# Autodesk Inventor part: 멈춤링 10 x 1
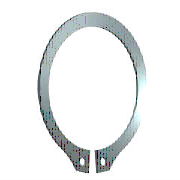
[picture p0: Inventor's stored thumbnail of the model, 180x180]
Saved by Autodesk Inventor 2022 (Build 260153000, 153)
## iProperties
Created: 2021-07
Part Number: 멈춤링 10 x 1
Material: 강철, 연강
Description: 리테이닝 링(C형)
Document SubType Name: Modeling
Standard: KS B 1336
Designer: mdu
Standards Organization: KS
Language: ko-KR
Size Designation: 10 x 1
Categories: <MemberInstance><Categories><Category DisplayName="샤프트 부품" InternalName="7f7aeb1f-a693-4053-b835-cee3144e0d98" Mnemonic="SHFT"><Category DisplayName="써클립" Inter
Density: 7.86 g/cm^3
Mass: 0.423084 g
Surface Area: 1.9243 cm^2
Volume: 0.0538275 cm^3
Appearance: 파란색 - 벽 페인트 - 광택
IsCustomPart: 0
Author: mdu
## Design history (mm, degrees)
sketch "스케치1"
  geometry: L1 (-6, 0)-(6, 0) reference; L2 (0, 20.189)-(0, -80.536) reference; L3 (-48.09, 0)-(48.09, 0) reference; L4 (-0.3, -9.791)-(-0.3, -12.791); L5 (-0.3, -6.54)-(-0.3, -13.29); L6 (-2.795, 1.6)-(3.672, 1.6); L7 (0.3, -6.54)-(0.3, -13.29); L8 (0.3, -9.791)-(0.3, -12.791); C1 r 0.6 at (-1.2, -11.486); C2 r 0.6 at (1.2, -11.486); A1 r 4.8 centre (0, -5) between (0.3, -9.791) and (-0.3, -9.791); A2 r 6.2 centre (0, -4.6) between (2.988, -10.033) and (-2.988, -10.033); A3 r 7.796 centre (0, -5) between (-1.418, -12.666) and (-0.3, -12.791); A4 r 1.2 centre (-1.2, -11.486) between (-2.383, -11.285) and (-1.418, -12.666); A5 r 1.2 centre (-3.566, -11.084) between (-2.383, -11.285) and (-2.988, -10.033); A6 r 1.2 centre (3.566, -11.084) between (2.988, -10.033) and (2.383, -11.285); A7 r 1.2 centre (1.2, -11.486) between (1.418, -12.666) and (2.383, -11.285); A8 r 7.796 centre (0, -5) between (0.3, -12.791) and (1.418, -12.666)
  constraints: 16 point on circle, 12 end point, 10 centre point, 9 symmetric about line, 5 point on line, 4 tangent, 3 coincident, 2 horizontal, 1 perpendicular, 1 vertical, 5 other
  dimensions: "d0" = 9.6 diameter of A1 (= ND); "d1" = 3 distance of L4.end L4.start (= SRB2); "d6" = 0.3 distance between parallel lines of L2 L5 (= 0.25 x SD5); "d7" = 1.6 distance between parallel lines of L6 L3 (= SRB1); "d8" = 0.4 distance of A1.centre A2.centre (= 0.25 x SRB1); "d9" = 1.2 radius of A4 (= SD5); "d10" = 1.2 radius of A5 (= SD5); "d11" = 0.9 distance from line of L4 A4.centre (= 0.75 x SD5); "d12" = 1.2 diameter of C1 (= SD5); "d13" = 1.2 diameter of C2 (= SD5); "d14" = 5 distance from line of A1.centre L1 (= 0.5 x WD)
extrude "본체" new body sketch "스케치1" distance "d2" = 1 (= SD); taper "d3" = 0 deg
workaxis "Work Axis1"
workplane "Work Plane1"
body "Solid1"
other parameters: "SD" = 1 [user parameter; used in 1 equation term], "SRB1" = 1.6 [user parameter; used in 2 equation terms], "ND" = 9.6 [user parameter; used in 1 equation term], "SRB2" = 3 [user parameter; used in 1 equation term], "SD5" = 1.2 [user parameter; used in 6 equation terms], "d15" = 0, "d16" = 0, "d17" = 0, "d41" = 0, "d42" = 0, "SD3" = 9.3 [user parameter], "WDMAX" = 11 [user parameter]
